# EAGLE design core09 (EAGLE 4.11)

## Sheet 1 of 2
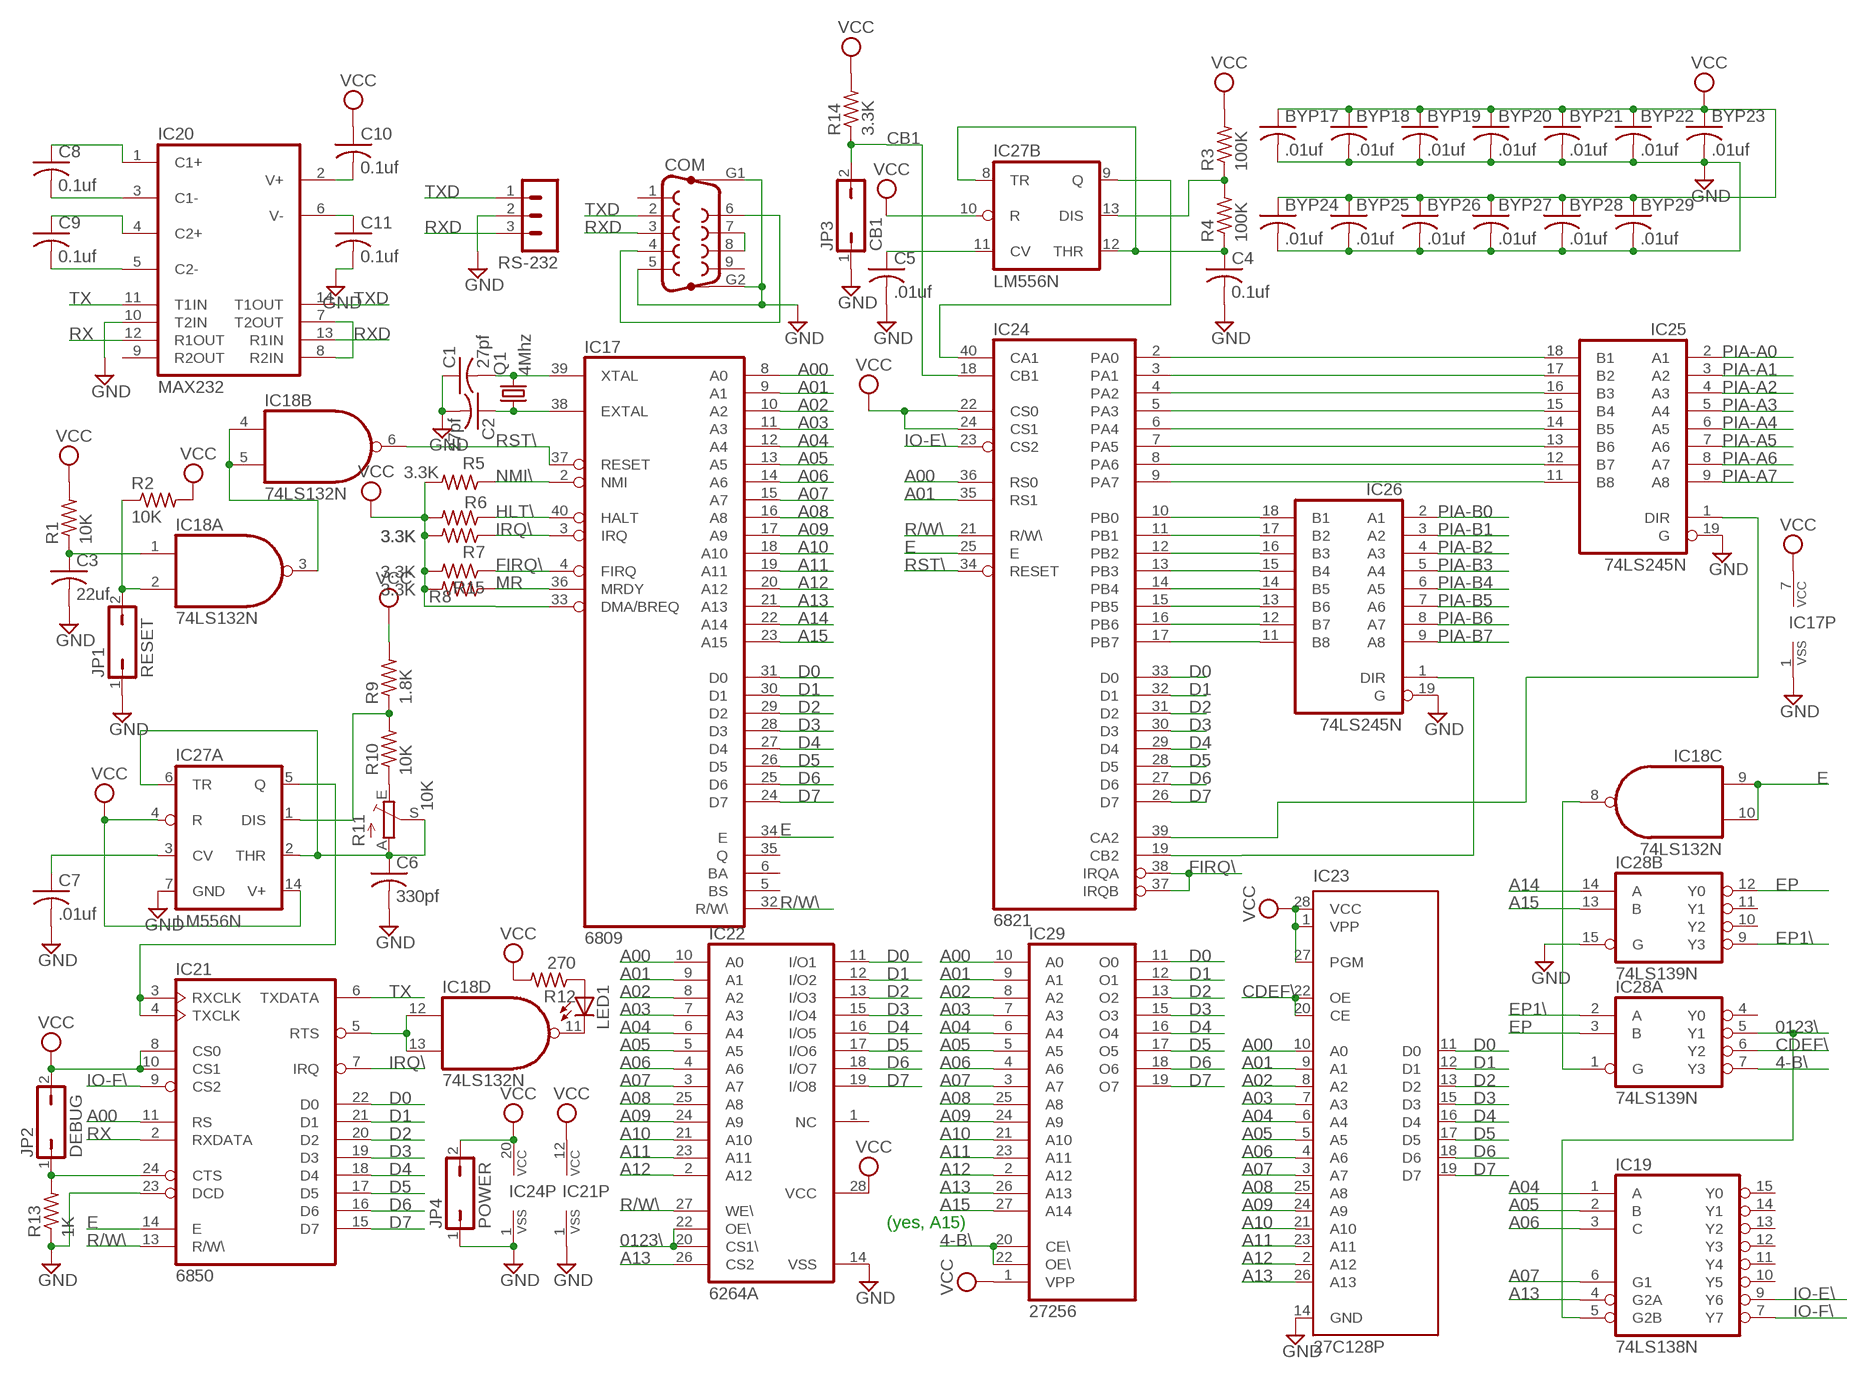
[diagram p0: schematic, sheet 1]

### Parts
BYP17  .01uf  C-US050-025X075  [C050-025X075]
BYP18  .01uf  C-US050-025X075  [C050-025X075]
BYP19  .01uf  C-US050-025X075  [C050-025X075]
BYP20  .01uf  C-US050-025X075  [C050-025X075]
BYP21  .01uf  C-US050-025X075  [C050-025X075]
BYP22  .01uf  C-US050-025X075  [C050-025X075]
BYP23  .01uf  C-US050-025X075  [C050-025X075]
BYP24  .01uf  C-US050-025X075  [C050-025X075]
BYP25  .01uf  C-US050-025X075  [C050-025X075]
BYP26  .01uf  C-US050-025X075  [C050-025X075]
BYP27  .01uf  C-US050-025X075  [C050-025X075]
BYP28  .01uf  C-US050-025X075  [C050-025X075]
BYP29  .01uf  C-US050-025X075  [C050-025X075]
C1  27pf  C-US050-025X075  [C050-025X075]
C2  27pf  C-US050-025X075  [C050-025X075]
C3  22uf  C-US102-043X133  [C102-043X133]
C4  0.1uf  C-US050-025X075  [C050-025X075]
C5  .01uf  C-US050-025X075  [C050-025X075]
C6  330pf  C-US050-025X075  [C050-025X075]
C7  .01uf  C-US050-025X075  [C050-025X075]
C8  0.1uf  C-US050-025X075  [C050-025X075]
C9  0.1uf  C-US050-025X075  [C050-025X075]
C10  0.1uf  C-US050-025X075  [C050-025X075]
C11  0.1uf  C-US050-025X075  [C050-025X075]
COM  F09HP  [F09HP]
IC17  6809  [DIL40]
IC18  74LS132N  74LS00N  [DIL14]
IC19  74LS138N  [DIL16]
IC20  MAX232  [DIL16]
IC21  6850  [DIL24]
IC22  6264A  [DIL28-6]
IC23  27C128P  [DIL28-6]
IC24  6821  [DIL40]
IC25  74LS245N  [DIL20]
IC26  74LS245N  [DIL20]
IC27  LM556N  [DIL14]
IC28  74LS139N  [DIL16]
IC29  27256  [DIL28]
JP1  RESET  JP1Q  [JP1]
JP2  DEBUG  JP1Q  [JP1]
JP3  CB1  JP1Q  [JP1]
JP4  POWER  JP1Q  [JP1]
LED1  LED3MM  [LED3MM]
Q1  4Mhz  CRYTALHC18U-V  [HC18U-V]
R1  10K  R-US_0207/7  [0207/7]
R2  10K  R-US_0207/7  [0207/7]
R3  100K  R-US_0207/7  [0207/7]
R4  100K  R-US_0207/7  [0207/7]
R5  3.3K  R-US_0207/7  [0207/7]
R6  3.3K  R-US_0207/7  [0207/7]
R7  3.3K  R-US_0207/7  [0207/7]
R8  3.3K  R-US_0207/7  [0207/7]
R9  1.8K  R-US_0207/7  [0207/7]
R10  10K  R-US_0207/7  [0207/7]
R11  10K  TRIM_EU-B90P  [SP19L]
R12  270  R-US_0207/7  [0207/7]
R13  1K  R-US_0207/7  [0207/7]
R14  3.3K  R-US_0207/7  [0207/7]
R15  3.3K  R-US_0207/7  [0207/7]
RS-232  MA03-1  [MA03-1]

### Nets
4-B\: IC28.7(A:Y3) IC29.20(CE\) IC29.22(OE\)
0123\: IC19.5(G2B) IC22.20(CS1\) IC22.22(OE\) IC28.5(A:Y1)
A00: IC17.8(A0) IC21.11(RS) IC22.10(A0) IC23.10(A0) IC24.36(RS0) IC29.10(A0)
A01: IC17.9(A1) IC22.9(A1) IC23.9(A1) IC24.35(RS1) IC29.9(A1)
A02: IC17.10(A2) IC22.8(A2) IC23.8(A2) IC29.8(A2)
A03: IC17.11(A3) IC22.7(A3) IC23.7(A3) IC29.7(A3)
A04: IC17.12(A4) IC19.1(A) IC22.6(A4) IC23.6(A4) IC29.6(A4)
A05: IC17.13(A5) IC19.2(B) IC22.5(A5) IC23.5(A5) IC29.5(A5)
A06: IC17.14(A6) IC19.3(C) IC22.4(A6) IC23.4(A6) IC29.4(A6)
A07: IC17.15(A7) IC19.6(G1) IC22.3(A7) IC23.3(A7) IC29.3(A7)
A08: IC17.16(A8) IC22.25(A8) IC23.25(A8) IC29.25(A8)
A09: IC17.17(A9) IC22.24(A9) IC23.24(A9) IC29.24(A9)
A10: IC17.18(A10) IC22.21(A10) IC23.21(A10) IC29.21(A10)
A11: IC17.19(A11) IC22.23(A11) IC23.23(A11) IC29.23(A11)
A12: IC17.20(A12) IC22.2(A12) IC23.2(A12) IC29.2(A12)
A13: IC17.21(A13) IC19.4(G2A) IC22.26(CS2) IC23.26(A13) IC29.26(A13)
A14: IC17.22(A14) IC28.14(B:A)
A15: IC17.23(A15) IC28.13(B:B) IC29.27(A14)
CB1: IC24.18(CB1) JP3.2 R14.1
CDEF\: IC23.20(CE) IC23.22(OE) IC28.6(A:Y2)
D0: IC17.31(D0) IC21.22(D0) IC22.11(I/O1) IC23.11(D0) IC24.33(D0) IC29.11(O0)
D1: IC17.30(D1) IC21.21(D1) IC22.12(I/O2) IC23.12(D1) IC24.32(D1) IC29.12(O1)
D2: IC17.29(D2) IC21.20(D2) IC22.13(I/O3) IC23.13(D2) IC24.31(D2) IC29.13(O2)
D3: IC17.28(D3) IC21.19(D3) IC22.15(I/O4) IC23.15(D3) IC24.30(D3) IC29.15(O3)
D4: IC17.27(D4) IC21.18(D4) IC22.16(I/O5) IC23.16(D4) IC24.29(D4) IC29.16(O4)
D5: IC17.26(D5) IC21.17(D5) IC22.17(I/O6) IC23.17(D5) IC24.28(D5) IC29.17(O5)
D6: IC17.25(D6) IC21.16(D6) IC22.18(I/O7) IC23.18(D6) IC24.27(D6) IC29.18(O6)
D7: IC17.24(D7) IC21.15(D7) IC22.19(I/O8) IC23.19(D7) IC24.26(D7) IC29.19(O7)
E: IC17.34(E) IC18.9(C:I0) IC18.10(C:I1) IC21.14(E) IC24.25(E)
EP: IC28.3(A:B) IC28.12(B:Y0)
EP1\: IC28.2(A:A) IC28.9(B:Y3)
FIRQ\ [Power]: IC17.4(FIRQ) IC24.37(IRQB) IC24.38(IRQA) R15.1
GND [Power]: BYP17.2 BYP18.2 BYP19.2 BYP20.2 BYP21.2 BYP22.2 BYP23.2 BYP24.2 BYP25.2 BYP26.2 BYP27.2 BYP28.2 BYP29.2 C1.1 C2.2 C3.2 C4.2 C5.2 C6.2 C7.2 C11.2 COM.5 COM.G1 COM.G2 IC17.1(VSS) IC20.10(T2IN) IC21.1(VSS) IC21.23(DCD) IC22.14(VSS) IC23.14(GND) IC24.1(VSS) IC25.19(G) IC26.19(G) IC27.7(A:GND) IC28.15(B:G) JP1.1 JP3.1 JP4.1 R13.1 RS-232.2 ; also sheet 2
HLT\: IC17.40(HALT) R5.1
IO-E\: IC19.9(Y6) IC24.23(CS2)
IO-F\: IC19.7(Y7) IC21.9(CS2)
IRQ\: IC17.3(IRQ) IC21.7(IRQ) R7.1
MR: IC17.36(MRDY) R8.1
N$1: COM.4 COM.6
N$3: C2.1 IC17.38(EXTAL) Q1.1
N$4: C1.2 IC17.39(XTAL) Q1.2
N$5: IC24.2(PA0) IC25.18(B1)
N$6: IC18.3(A:O) IC18.4(B:I0) IC18.5(B:I1)
N$21: C3.1 IC18.1(A:I0) R1.1
N$22: IC18.2(A:I1) JP1.2 R2.1
N$23: IC21.3(RXCLK) IC21.4(TXCLK) IC27.5(A:Q)
N$24: IC24.10(PB0) IC26.18(B1)
N$25: IC24.11(PB1) IC26.17(B2)
N$27: C6.1 IC27.2(A:THR) IC27.6(A:TR) R11.A R11.S
N$28: IC27.1(A:DIS) R9.1 R10.2
N$94: IC24.12(PB2) IC26.16(B3)
N$124: IC24.13(PB3) IC26.15(B4)
N$125: IC24.14(PB4) IC26.14(B5)
N$126: IC24.15(PB5) IC26.13(B6)
N$127: IC24.16(PB6) IC26.12(B7)
N$128: IC24.17(PB7) IC26.11(B8)
N$129: IC24.3(PA1) IC25.17(B2)
N$130: IC24.4(PA2) IC25.16(B3)
N$131: IC24.5(PA3) IC25.15(B4)
N$132: IC24.6(PA4) IC25.14(B5)
N$133: IC24.7(PA5) IC25.13(B6)
N$134: IC24.8(PA6) IC25.12(B7)
N$135: IC24.9(PA7) IC25.11(B8)
N$136: IC24.19(CB2) IC26.1(DIR)
N$137: IC24.39(CA2) IC25.1(DIR)
N$138: IC24.40(CA1) IC27.9(B:Q)
N$140: C4.1 IC27.8(B:TR) IC27.12(B:THR) R4.1
N$141: IC27.13(B:DIS) R3.1 R4.2
N$142: C5.1 IC27.11(B:CV)
N$143: R10.1 R11.E
N$145: COM.7 COM.8
N$147: IC18.12(D:I0) IC18.13(D:I1) IC21.5(RTS)
N$148: IC18.11(D:O) LED1.K(C)
N$149: LED1.A R12.1
N$150: IC21.24(CTS) JP2.1 R13.2
N$151: IC18.8(C:O) IC28.1(A:G)
N$153: IC20.7(T2OUT) IC20.8(R2IN)
N$154: C7.1 IC27.3(A:CV)
N$155: C9.2 IC20.5(C2-)
N$156: C9.1 IC20.4(C2+)
N$157: C8.2 IC20.3(C1-)
N$158: C8.1 IC20.1(C1+)
N$159: C11.1 IC20.6(V-)
N$160: C10.2 IC20.2(V+)
NMI\: IC17.2(NMI) R6.1
PIA-A0: IC25.2(A1) ; also sheet 2
PIA-A1: IC25.3(A2) ; also sheet 2
PIA-A2: IC25.4(A3) ; also sheet 2
PIA-A3: IC25.5(A4) ; also sheet 2
PIA-A4: IC25.6(A5) ; also sheet 2
PIA-A5: IC25.7(A6) ; also sheet 2
PIA-A6: IC25.8(A7) ; also sheet 2
PIA-A7: IC25.9(A8) ; also sheet 2
PIA-B0: IC26.2(A1) ; also sheet 2
PIA-B1: IC26.3(A2) ; also sheet 2
PIA-B2: IC26.4(A3) ; also sheet 2
PIA-B3: IC26.5(A4) ; also sheet 2
PIA-B4: IC26.6(A5) ; also sheet 2
PIA-B5: IC26.7(A6) ; also sheet 2
PIA-B6: IC26.8(A7) ; also sheet 2
PIA-B7: IC26.9(A8) ; also sheet 2
R/W\: IC17.32(R/W\) IC21.13(R/W\) IC22.27(WE\) IC24.21(R/W\)
RST\: IC17.37(RESET) IC18.6(B:O) IC24.34(RESET)
RX: IC20.12(R1OUT) IC21.2(RXDATA)
RXD: COM.3 IC20.13(R1IN) RS-232.3
TX: IC20.11(T1IN) IC21.6(TXDATA)
TXD: COM.2 IC20.14(T1OUT) RS-232.1
VCC [Power]: BYP17.1 BYP18.1 BYP19.1 BYP20.1 BYP21.1 BYP22.1 BYP23.1 BYP24.1 BYP25.1 BYP26.1 BYP27.1 BYP28.1 BYP29.1 C10.1 IC17.7(VCC) IC17.33(DMA/BREQ) IC21.8(CS0) IC21.10(CS1) IC21.12(VCC) IC22.28(VCC) IC23.1(VPP) IC23.27(PGM) IC23.28(VCC) IC24.20(VCC) IC24.22(CS0) IC24.24(CS1) IC27.4(A:R) IC27.10(B:R) IC27.14(A:V+) IC29.1(VPP) JP2.2 JP4.2 R1.2 R2.2 R3.2 R5.2 R6.2 R7.2 R8.2 R9.2 R12.2 R14.2 R15.2 ; also sheet 2
Unconnected: COM.1 COM.9 IC17.5(BS) IC17.6(BA) IC17.35(Q) IC19.10(Y5) IC19.11(Y4) IC19.12(Y3) IC19.13(Y2) IC19.14(Y1) IC19.15(Y0) IC20.9(R2OUT) IC22.1(NC) IC28.4(A:Y0) IC28.10(B:Y2) IC28.11(B:Y1)

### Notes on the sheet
- (yes, A15)

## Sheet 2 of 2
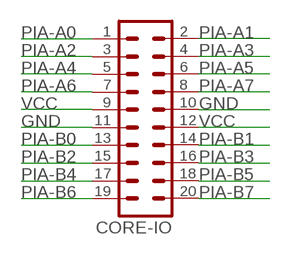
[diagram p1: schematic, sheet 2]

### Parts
CORE-IO  MA10-2  [MA10-2]

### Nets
GND [Power]: CORE-IO.10 CORE-IO.11 ; also sheet 1
PIA-A0: CORE-IO.1 ; also sheet 1
PIA-A1: CORE-IO.2 ; also sheet 1
PIA-A2: CORE-IO.3 ; also sheet 1
PIA-A3: CORE-IO.4 ; also sheet 1
PIA-A4: CORE-IO.5 ; also sheet 1
PIA-A5: CORE-IO.6 ; also sheet 1
PIA-A6: CORE-IO.7 ; also sheet 1
PIA-A7: CORE-IO.8 ; also sheet 1
PIA-B0: CORE-IO.13 ; also sheet 1
PIA-B1: CORE-IO.14 ; also sheet 1
PIA-B2: CORE-IO.15 ; also sheet 1
PIA-B3: CORE-IO.16 ; also sheet 1
PIA-B4: CORE-IO.17 ; also sheet 1
PIA-B5: CORE-IO.18 ; also sheet 1
PIA-B6: CORE-IO.19 ; also sheet 1
PIA-B7: CORE-IO.20 ; also sheet 1
VCC [Power]: CORE-IO.9 CORE-IO.12 ; also sheet 1

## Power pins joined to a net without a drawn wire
GND: IC18.7(P:GND) IC19.8(GND) IC20.15(GND) IC25.10(GND) IC26.10(GND) IC28.8(P:GND) IC29.14(GND)
VCC: IC18.14(P:VCC) IC19.16(VCC) IC20.16(VCC) IC25.20(VCC) IC26.20(VCC) IC28.16(P:VCC) IC29.28(VCC)

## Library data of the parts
BYP17-BYP29 C1-C11 = rcl:C-US: CAPACITOR, American symbol
COM = con-subd:F09HP: SUB-D
CORE-IO = con-lstb:MA10-2: PIN HEADER
IC17 = micro-motorola:6809: MICROCONTROLLER/MEMORY DEVICE
IC18 = 74xx-us:74*00: Quad 2-input NAND gate
IC19 = 74xx-us:74*138: 3-line to 8-line DECODER/DEMULTIPLEXER
IC20 = maxim:MAX232: RS232 TRANSEIVER
IC21 = micro-motorola:6850: MICROCONTROLLER/MEMORY DEVICE
IC22 = memory-hitachi:6264A: MEMORY
IC23 = microchip:27*128: CMOS EPROM 128 K (16 K x 8)
IC24 = micro-motorola:6821: MICROCONTROLLER/MEMORY DEVICE
IC25 IC26 = 74xx-us:74*245: Octal BUS TRANSCEIVER, 3-state
IC27 = linear:*556: Dual TIMER
IC28 = 74xx-us:74*139: Dual 2-line to 4-line DECODER/DEMULTIPLEXER
IC29 = memory:27256: MEMORY
JP1-JP4 = jumper:JP1Q: JUMPER
LED1 = led:LED: LED
Q1 = crystal:CRYTAL: CRYSTAL
R1-R10 R12-R15 = rcl:R-US_: RESISTOR, American symbol
R11 = pot:TRIM_EU-: POTENTIOMETER
RS-232 = con-lstb:MA03-1: PIN HEADER

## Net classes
1 Power: width 0.508 mm, drill 0.254 mm, clearance 0.254 mm

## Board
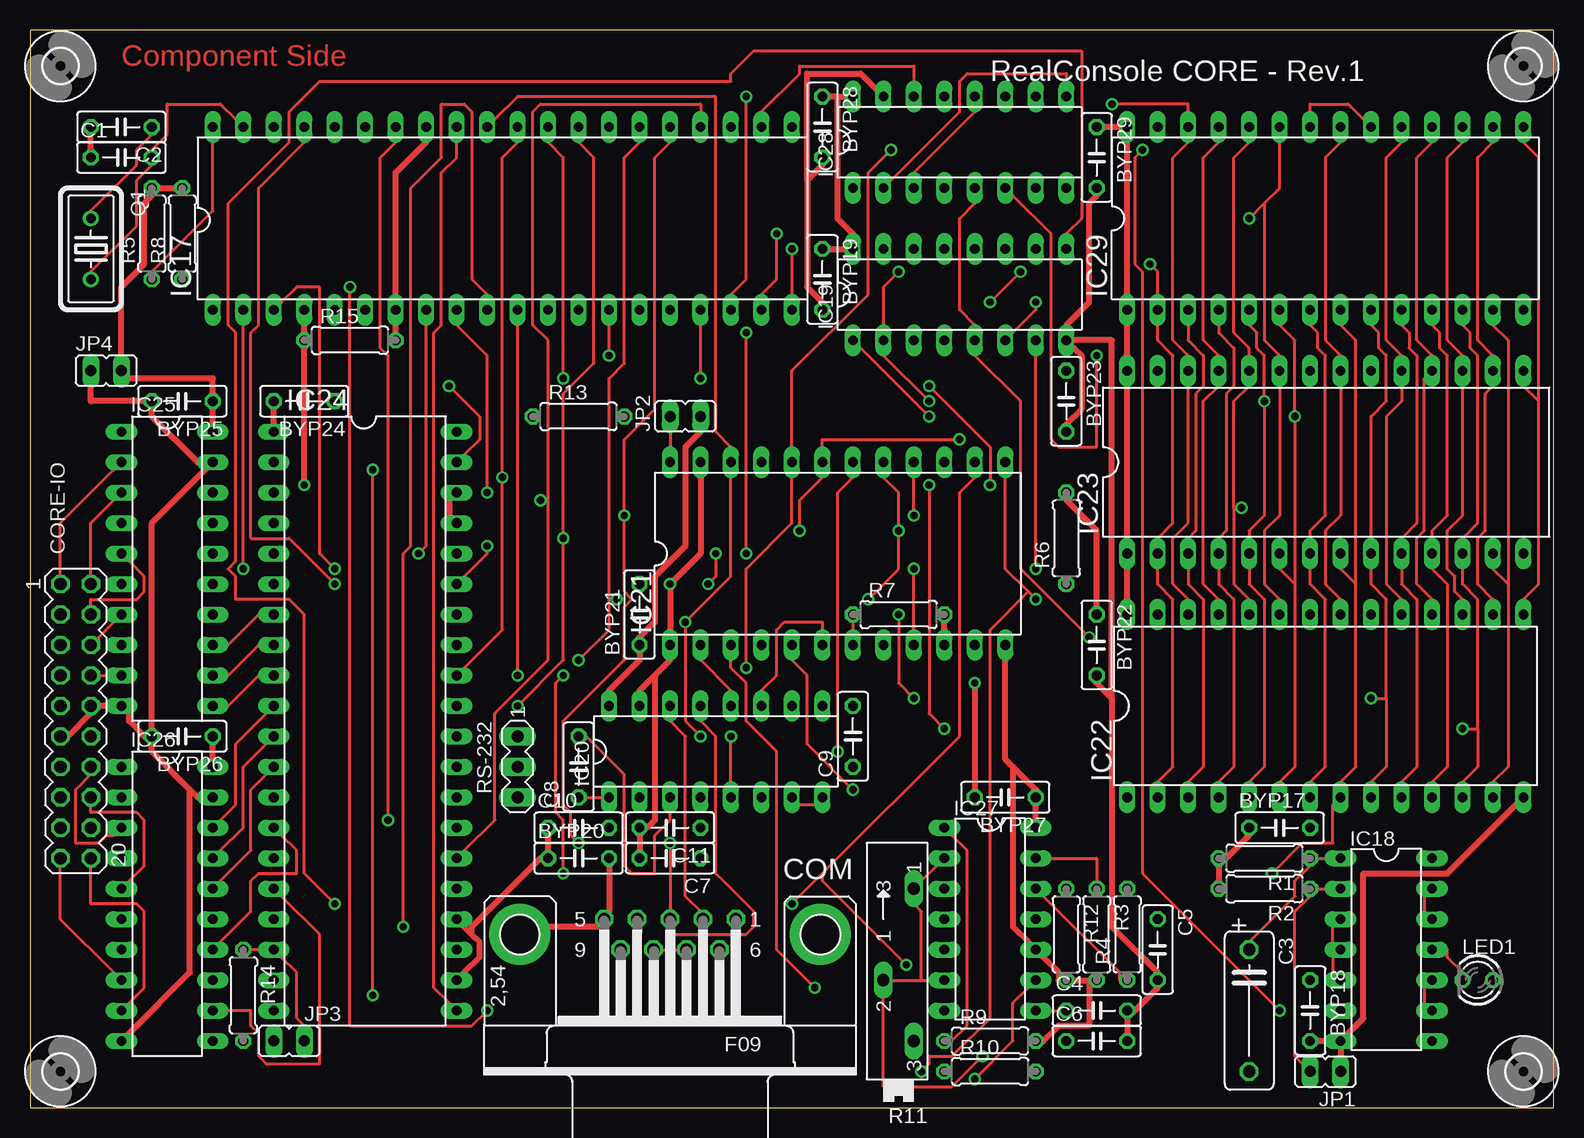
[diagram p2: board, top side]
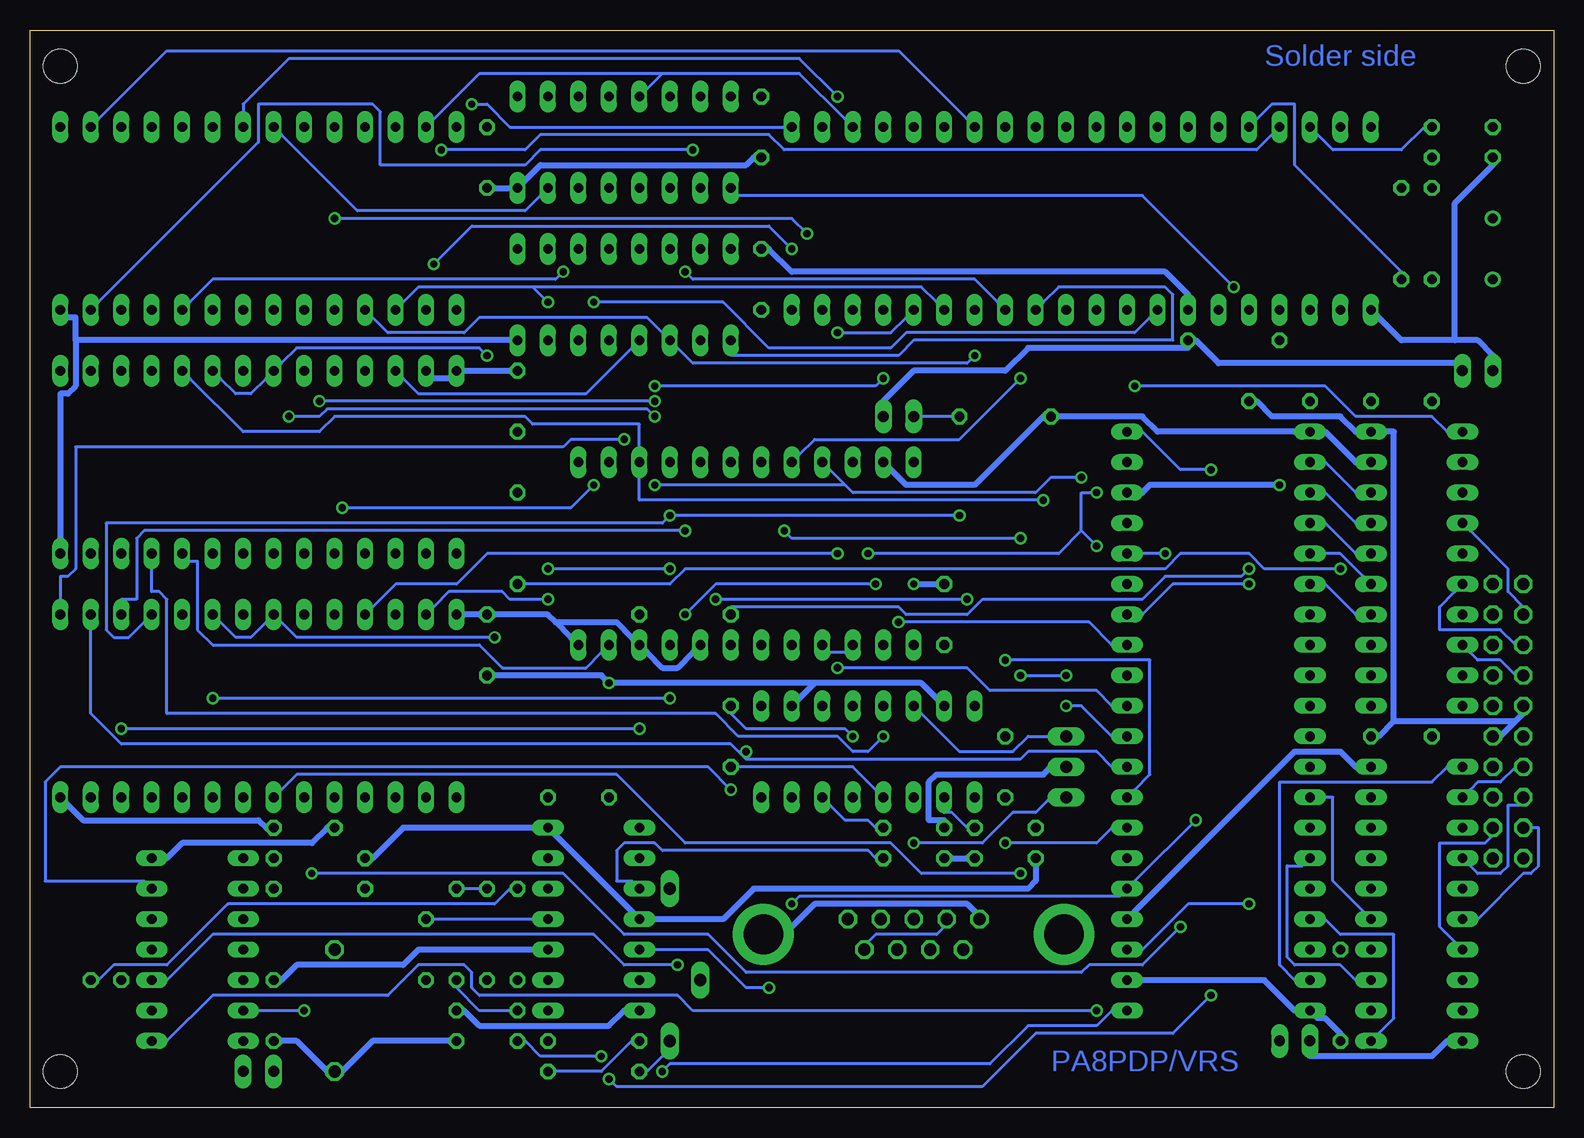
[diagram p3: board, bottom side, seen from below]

Size 126.98 x 89.84 mm. Coordinates in mm from the lower left corner, seen from the top.
Outline: 0,0 126.98,0 126.98,89.84 0,89.84 0,0
Copper layers (1*16): Top 0.035mm / dielectric 1.5mm / Bottom 0.035mm
Design rules "olimex10mil": minimum track width 10mil, minimum drill 24mil, track to track 10mil, track to pad 10mil, pad to pad 10mil, via to via 10mil, smd to smd 10mil, copper to edge 40mil, drill to drill 10mil, minimum pad ring 10mil, minimum via ring 8mil, stop-mask expansion 0mil, vias tented up to drill 0mil, thermal gap 10mil

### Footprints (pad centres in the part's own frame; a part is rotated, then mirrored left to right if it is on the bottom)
C050-025X075 = drill 0.813 octagon: 1 -2.54,0; 2 2.54,0
C102-043X133 = drill 1.016 octagon: 1 -5.08,0; 2 5.08,0
F09HP = drill 1.016 octagon: 1 -5.486,-1.27; 2 -2.743,-1.27; 3 0,-1.27; 4 2.743,-1.27; 5 5.486,-1.27; 6 -4.115,1.27; 7 -1.372,1.27; 8 1.372,1.27; 9 4.115,1.27 | drill 3.302 pad 5.08 round: G1 -12.522,0; G2 12.522,0
MA10-2 = drill 1.016 octagon: 1 -11.43,-1.27; 2 -11.43,1.27; 3 -8.89,-1.27; 4 -8.89,1.27; 5 -6.35,-1.27; 6 -6.35,1.27; 7 -3.81,-1.27; 8 -3.81,1.27; 9 -1.27,-1.27; 10 -1.27,1.27; 11 1.27,-1.27; 12 1.27,1.27; 13 3.81,-1.27; 14 3.81,1.27; 15 6.35,-1.27; 16 6.35,1.27; 17 8.89,-1.27; 18 8.89,1.27; 19 11.43,-1.27; 20 11.43,1.27
DIL40 = drill 0.813 long: 1 -24.13,-7.62; 2 -21.59,-7.62; 3 -19.05,-7.62; 4 -16.51,-7.62; 5 -13.97,-7.62; 6 -11.43,-7.62; 7 -8.89,-7.62; 8 -6.35,-7.62; 9 -3.81,-7.62; 10 -1.27,-7.62; 11 1.27,-7.62; 12 3.81,-7.62; 13 6.35,-7.62; 14 8.89,-7.62; 15 11.43,-7.62; 16 13.97,-7.62; 17 16.51,-7.62; 18 19.05,-7.62; 19 21.59,-7.62; 20 24.13,-7.62; 21 24.13,7.62; 22 21.59,7.62; 23 19.05,7.62; 24 16.51,7.62; 25 13.97,7.62; 26 11.43,7.62; 27 8.89,7.62; 28 6.35,7.62; 29 3.81,7.62; 30 1.27,7.62; 31 -1.27,7.62; 32 -3.81,7.62; 33 -6.35,7.62; 34 -8.89,7.62; 35 -11.43,7.62; 36 -13.97,7.62; 37 -16.51,7.62; 38 -19.05,7.62; 39 -21.59,7.62; 40 -24.13,7.62
DIL14 = drill 0.813 long: 1 -7.62,-3.81; 2 -5.08,-3.81; 3 -2.54,-3.81; 4 0,-3.81; 5 2.54,-3.81; 6 5.08,-3.81; 7 7.62,-3.81; 8 7.62,3.81; 9 5.08,3.81; 10 2.54,3.81; 11 0,3.81; 12 -2.54,3.81; 13 -5.08,3.81; 14 -7.62,3.81
DIL16 = drill 0.813 long: 1 -8.89,-3.81; 2 -6.35,-3.81; 3 -3.81,-3.81; 4 -1.27,-3.81; 5 1.27,-3.81; 6 3.81,-3.81; 7 6.35,-3.81; 8 8.89,-3.81; 9 8.89,3.81; 10 6.35,3.81; 11 3.81,3.81; 12 1.27,3.81; 13 -1.27,3.81; 14 -3.81,3.81; 15 -6.35,3.81; 16 -8.89,3.81
DIL24 = drill 0.813 long: 1 -13.97,-7.62; 2 -11.43,-7.62; 3 -8.89,-7.62; 4 -6.35,-7.62; 5 -3.81,-7.62; 6 -1.27,-7.62; 7 1.27,-7.62; 8 3.81,-7.62; 9 6.35,-7.62; 10 8.89,-7.62; 11 11.43,-7.62; 12 13.97,-7.62; 13 13.97,7.62; 14 11.43,7.62; 15 8.89,7.62; 16 6.35,7.62; 17 3.81,7.62; 18 1.27,7.62; 19 -1.27,7.62; 20 -3.81,7.62; 21 -6.35,7.62; 22 -8.89,7.62; 23 -11.43,7.62; 24 -13.97,7.62
DIL28-6 = drill 0.813 long: 1 -16.51,-7.62; 2 -13.97,-7.62; 3 -11.43,-7.62; 4 -8.89,-7.62; 5 -6.35,-7.62; 6 -3.81,-7.62; 7 -1.27,-7.62; 8 1.27,-7.62; 9 3.81,-7.62; 10 6.35,-7.62; 11 8.89,-7.62; 12 11.43,-7.62; 13 13.97,-7.62; 14 16.51,-7.62; 15 16.51,7.62; 16 13.97,7.62; 17 11.43,7.62; 18 8.89,7.62; 19 6.35,7.62; 20 3.81,7.62; 21 1.27,7.62; 22 -1.27,7.62; 23 -3.81,7.62; 24 -6.35,7.62; 25 -8.89,7.62; 26 -11.43,7.62; 27 -13.97,7.62; 28 -16.51,7.62
DIL20 = drill 0.813 long: 1 -11.43,-3.81; 2 -8.89,-3.81; 3 -6.35,-3.81; 4 -3.81,-3.81; 5 -1.27,-3.81; 6 1.27,-3.81; 7 3.81,-3.81; 8 6.35,-3.81; 9 8.89,-3.81; 10 11.43,-3.81; 11 11.43,3.81; 12 8.89,3.81; 13 6.35,3.81; 14 3.81,3.81; 15 1.27,3.81; 16 -1.27,3.81; 17 -3.81,3.81; 18 -6.35,3.81; 19 -8.89,3.81; 20 -11.43,3.81
DIL28 = drill 0.813 long: 1 -16.51,-7.62; 2 -13.97,-7.62; 3 -11.43,-7.62; 4 -8.89,-7.62; 5 -6.35,-7.62; 6 -3.81,-7.62; 7 -1.27,-7.62; 8 1.27,-7.62; 9 3.81,-7.62; 10 6.35,-7.62; 11 8.89,-7.62; 12 11.43,-7.62; 13 13.97,-7.62; 14 16.51,-7.62; 15 16.51,7.62; 16 13.97,7.62; 17 11.43,7.62; 18 8.89,7.62; 19 6.35,7.62; 20 3.81,7.62; 21 1.27,7.62; 22 -1.27,7.62; 23 -3.81,7.62; 24 -6.35,7.62; 25 -8.89,7.62; 26 -11.43,7.62; 27 -13.97,7.62; 28 -16.51,7.62
JP1 = drill 0.914 long: 1 0,-1.27; 2 0,1.27
LED3MM = drill 0.813 octagon: A -1.27,0; K 1.27,0
HC18U-V = drill 0.813 round: 1 -2.54,0; 2 2.54,0
0207/7 = drill 0.813 octagon: 1 -3.81,0; 2 3.81,0
SP19L = drill 1.016 long: A 5.715,-1.27; E -6.985,-1.27; S -1.905,1.27
MA03-1 = drill 1.016 long: 1 -2.54,0; 2 0,0; 3 2.54,0
2,8 = hole 2.8: 0,0

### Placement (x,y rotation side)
BYP17  104.14,23.33 0 top
BYP18  106.68,8.09 270 top
BYP19  66.04,69.05 270 top
BYP20  45.71,20.79 0 top
BYP21  50.79,41.11 90 top
BYP22  88.9,38.57 270 top
BYP23  86.36,58.89 270 top
BYP24  22.86,58.89 180 top
BYP25  12.69,58.89 180 top
BYP26  12.69,30.95 180 top
BYP27  81.28,25.87 180 top
BYP28  66.04,81.75 270 top
BYP29  88.9,79.21 270 top
C1  7.62,79.21 0 top
C2  7.62,81.75 180 top
C3  101.59,8.09 270 top
C4  88.9,8.09 0 top
C5  93.98,13.17 270 top
C6  88.9,5.55 0 top
C7  53.34,20.79 180 top
C8  45.71,28.41 90 top
C9  68.58,30.95 90 top
C10  45.71,23.33 0 top
C11  53.34,23.33 180 top
COM  53.34,14.44 180 top
CORE-IO  3.81,32.22 270 top
IC17  39.36,74.13 0 top
IC18  113.03,13.17 270 top
IC19  77.47,67.78 0 top
IC20  57.14,29.68 0 top
IC21  67.31,46.19 0 top
IC22  107.95,33.49 0 top
IC23  107.95,53.81 0 top
IC24  27.94,32.22 270 top
IC25  11.42,44.92 270 top
IC26  11.42,16.98 270 top
IC27  80.01,15.71 270 top
IC28  77.47,80.48 0 top
IC29  107.95,74.13 0 top
JP1  107.95,3.01 90 top
JP2  54.6,57.62 270 top
JP3  21.59,5.55 270 top
JP4  6.34,61.43 270 top
LED1  120.65,10.63 180 top
Q1  5.08,71.59 270 top
R1  102.87,20.79 180 top
R2  102.87,18.25 180 top
R3  88.9,14.44 270 top
R4  91.44,14.44 90 top
R5  10.15,72.86 90 top
R6  86.36,47.46 90 top
R7  72.39,41.11 0 top
R8  12.69,72.86 90 top
R9  80.01,5.55 0 top
R10  80.01,3.01 0 top
R11  72.39,12.54 90 top
R12  86.36,14.44 270 top
R13  45.71,57.62 0 top
R14  17.78,9.36 270 top
R15  26.67,63.97 0 top
RS-232  40.63,28.41 270 top
U$3  [2,8]  2.54,86.83 0 top
U$4  [2,8]  2.54,3.01 0 top
U$5  [2,8]  124.45,86.83 0 top
U$6  [2,8]  124.45,3.01 0 top

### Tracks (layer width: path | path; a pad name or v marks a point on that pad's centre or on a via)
4-B\
  Top 0.254: IC29.20 111.12,82.39 109.85,83.66 106.68,83.66 106.68,83.02 IC29.22
  Bottom 0.254: IC28.7 84.45,76.03 85.72,74.77 99.69,74.77 106.04,81.11 IC29.22
0123\  (via drill 0.61)
  Top 0.254: IC28.5 78.73,75.4 77.47,74.13 77.47,66.51 78.73,65.24 IC19.5 78.73,62.7 82.55,58.89 82.55,44.92 v88.26,39.2
  Bottom 0.254: IC22.20 111.12,40.48 109.85,39.2 108.58,39.2 107.31,40.48 IC22.22 106.04,40.48 104.77,39.2 v88.26,39.2
A00  (via drill 0.61)
  Top 0.254: v32.38,46.19 33.02,46.82 33.02,65.24 IC17.8 | IC22.10 114.3,27.14 115.56,28.41 115.56,42.38 114.3,43.65 114.3,44.92 IC23.10 114.3,47.46 115.56,48.73 115.56,62.7 114.93,63.34 114.93,64.61 114.3,65.24 IC29.10 | v80.01,67.14 v82.55,69.69
  Bottom 0.254: v32.38,46.19 34.28,46.19 IC24.36 | IC21.11 79.37,37.94 80.64,36.66 87.62,36.66 89.53,38.57 111.76,38.57 113.03,39.84 113.03,45.55 113.66,45.55 IC23.10 | v80.01,67.14 69.21,67.14 65.4,63.34 55.24,63.34 53.97,64.61 34.92,64.61 33.65,65.88 IC17.8 | v82.55,69.69 83.18,69.05 111.76,69.05 113.66,67.14 IC29.10
A01  (via drill 0.61)
  Top 0.254: v38.09,46.82 38.09,46.19 36.19,44.28 IC24.35 | v38.09,51.27 38.09,62.7 35.55,65.24 IC17.9 | IC29.9 111.76,65.24 112.39,64.61 112.39,63.34 113.03,62.7 113.03,58.89 111.76,57.62 111.76,47.46 IC23.9 111.76,44.92 111.76,43.65 113.03,42.38 113.03,34.12 | 113.03,34.12 113.03,28.41 111.76,27.14 IC22.9 | v111.76,34.12 113.03,34.12 | v73.66,34.12 72.39,35.39 v72.39,41.11 | v56.51,43.65 57.14,44.28 v57.14,46.19
  Bottom 0.254: v38.09,46.82 39.36,48.09 | 39.36,48.09 39.36,51.27 v38.09,51.27 | v73.66,34.12 v111.76,34.12 | v72.39,41.11 69.84,43.65 v56.51,43.65 | v57.14,46.19 41.27,46.19 39.36,48.09
A02  (via drill 0.61)
  Top 0.254: 110.48,43.65 110.48,28.41 109.22,27.14 IC22.8 108.58,25.23 108.58,22.06 106.04,22.06 v103.5,19.52 | 110.48,43.65 109.22,44.92 IC23.8 | v31.11,15.08 31.11,46.19 31.75,46.82 31.75,76.67 34.28,79.21 34.28,83.66 36.19,83.66 36.82,83.02 36.82,69.05 38.09,67.78 IC17.10 | 110.48,43.65 110.48,63.97 109.22,65.24 IC29.8
  Bottom 0.254: v31.11,15.08 34.28,11.9 38.73,11.9 39.36,11.27 67.31,11.27 70.48,14.44 77.47,14.44 82.55,19.52 v103.5,19.52
A03  (via drill 0.61)
  Top 0.254: IC22.7 106.68,27.14 107.95,28.41 107.95,42.38 106.68,43.65 106.68,44.92 IC23.7 106.68,47.46 106.68,48.09 107.95,49.37 107.95,62.7 107.31,63.34 107.31,64.61 106.68,65.24 IC29.7 | v40.63,36.03 40.63,65.24 IC17.11 | v44.45,36.03 43.81,35.39 43.81,24.6 44.45,23.96 v44.45,19.52
  Bottom 0.254: v44.45,36.03 v40.63,36.03 | v44.45,19.52 52.7,19.52 55.24,22.06 72.39,22.06 78.1,27.77 104.77,27.77 106.04,26.5 IC22.7
A04  (via drill 0.61)
  Top 0.254: 105.41,43.65 105.41,28.41 104.14,27.14 IC22.6 | 105.41,43.65 104.14,44.92 IC23.6 | 105.41,43.65 v105.41,57.62 105.41,63.97 104.14,65.24 IC29.6 | v74.93,57.62 69.21,63.34 IC19.1
  Bottom 0.254: IC17.12 42.54,67.14 41.27,68.41 32.38,68.41 31.75,67.78 31.75,63.97 53.34,63.97 54.6,62.7 68.58,62.7 IC19.1 | v74.93,57.62 75.56,58.25 102.23,58.25 102.87,57.62 v105.41,57.62
A05  (via drill 0.61)
  Top 0.254: v72.39,69.69 71.12,68.41 71.12,65.24 IC19.2 71.12,62.7 v74.93,58.89 | IC22.5 101.59,27.14 102.87,28.41 102.87,42.38 101.59,43.65 101.59,44.92 IC23.5 101.59,47.46 101.59,48.09 102.87,49.37 v102.87,58.89 102.87,62.7 102.23,63.34 102.23,64.61 101.59,65.24 IC29.5
  Bottom 0.254: v72.39,69.69 71.75,69.05 48.25,69.05 46.35,67.14 IC17.13 | v74.93,58.89 v102.87,58.89
A06  (via drill 0.61)
  Top 0.254: IC22.4 99.06,27.14 100.33,28.41 100.33,42.38 99.06,43.65 99.06,44.92 IC23.4 99.06,47.46 99.69,48.09 99.69,59.52 100.33,60.16 100.33,63.34 99.06,64.61 99.06,65.24 IC29.4 | v48.25,62.7 48.25,65.24 IC17.14
  Bottom 0.254: IC29.4 98.42,65.88 97.15,64.61 90.8,64.61 89.53,65.88 75.56,65.88 74.29,64.61 IC19.3 73.02,63.34 71.75,62.06 48.89,62.06 v48.25,62.7
A07  (via drill 0.61)
  Top 0.254: IC22.3 96.52,27.14 97.79,28.41 97.79,42.38 96.52,43.65 96.52,44.92 IC23.3 96.52,47.46 97.15,48.09 97.15,59.52 97.79,60.16 97.79,62.7 96.52,63.97 96.52,65.24 IC29.3 | v83.81,67.14 83.81,66.51 81.91,64.61 IC19.6
  Bottom 0.254: 85.09,68.41 v83.81,67.14 | 85.09,68.41 94.61,68.41 95.88,67.14 IC29.3 | 85.09,68.41 52.7,68.41 51.43,67.14 IC17.15
A08  (via drill 0.61)
  Top 0.254: IC22.25 99.06,42.38 97.79,43.65 97.79,58.89 99.06,60.16 IC23.25 99.06,62.7 97.79,63.97 97.79,79.21 99.06,80.48 IC29.25 | v59.68,46.19 v59.68,64.61
  Bottom 0.254: v59.68,64.61 55.24,64.61 53.97,65.88 IC17.16 | v59.68,46.19 88.9,46.19 91.44,43.65 96.52,43.65 98.42,41.74 IC22.25
A09  (via drill 0.61)
  Top 0.254: 100.33,50 100.33,58.89 101.59,60.16 IC23.24 101.59,62.7 101.59,63.34 100.33,64.61 100.33,79.21 101.59,80.48 IC29.24 | 100.33,50 100.33,43.65 101.59,42.38 IC22.24 | v55.88,60.8 55.88,65.24 IC17.17 | v74.93,60.16 80.01,55.08 v80.01,51.91 | v100.96,50 100.33,50
  Bottom 0.254: v55.88,60.8 56.51,60.16 v74.93,60.16 | v80.01,51.91 81.91,50 v100.96,50
A10  (via drill 0.61)
  Top 0.254: IC22.21 109.22,42.38 107.95,43.65 107.95,48.09 109.22,49.37 109.22,60.16 IC23.21 109.22,62.7 107.95,63.97 107.95,79.21 109.22,80.48 IC29.21 | v59.68,84.29 59.68,69.05 58.41,67.78 IC17.18
  Bottom 0.254: v59.68,84.29 62.86,87.47 105.41,87.47 109.22,83.66 109.22,83.02 IC29.21
A11  (via drill 0.61)
  Top 0.254: IC22.23 104.14,42.38 102.87,43.65 102.87,48.09 104.14,49.37 104.14,60.16 IC23.23 104.14,62.7 102.87,63.97 102.87,75.4 | v62.22,72.86 62.22,69.05 60.95,67.78 IC17.19 | 102.87,75.4 104.14,76.67 104.14,80.48 IC29.23 | v101.59,74.13 102.87,75.4
  Bottom 0.254: v62.22,72.86 63.49,74.13 v101.59,74.13
A12  (via drill 0.61)
  Top 0.254: IC22.2 93.98,27.14 95.25,28.41 95.25,42.38 93.98,43.65 93.98,44.92 IC23.2 93.98,47.46 95.25,48.73 95.25,62.7 93.98,63.97 93.98,65.24 IC29.2 93.98,67.78 93.98,69.69 v93.34,70.32 | v63.49,71.59 63.49,67.78 IC17.20
  Bottom 0.254: v63.49,71.59 65.4,73.5 90.17,73.5 v93.34,70.32
A13  (via drill 0.61)
  Top 0.254: v90.17,83.66 96.52,83.66 96.52,83.02 IC29.26 96.52,80.48 95.25,79.21 95.25,63.97 96.52,62.7 IC23.26 96.52,60.16 96.52,48.73 95.25,47.46 95.25,43.65 96.52,42.38 IC22.26
  Bottom 0.254: v90.17,83.66 88.9,83.66 86.99,81.75 64.13,81.75 IC17.21 | IC19.4 76.83,63.34 80.64,59.52 94.61,59.52 95.88,60.8 IC23.26
A14
  Top 0.254: IC17.22 60.95,83.02 64.13,86.19 64.13,86.83 73.66,86.83 73.66,85.56 IC28.14
A15
  Bottom 0.254: 74.29,86.19 62.86,86.19 59.05,82.39 IC17.23 | 74.29,86.19 75.56,84.92 IC28.13 | 74.29,86.19 89.53,86.19 93.34,82.39 IC29.27
CB1
  Top 0.254: R14.1 18.41,13.17 19.05,13.17 IC24.18 20.95,12.54 22.22,11.27 22.22,7.46 22.86,6.82 JP3.2
CDEF\  (via drill 0.61)
  Top 0.254: v88.9,62.7 88.9,55.08 85.72,55.08 85.09,55.71 85.09,72.86 81.91,76.03 IC28.6
  Bottom 0.254: IC23.20 111.12,60.8 109.85,59.52 108.58,59.52 107.31,60.8 IC23.22 106.04,62.06 104.77,63.34 89.53,63.34 v88.9,62.7
D0  (via drill 0.61)
  Top 0.254: IC22.11 116.84,27.14 118.11,28.41 118.11,43.65 116.84,44.92 IC23.11 116.84,47.46 116.84,48.09 118.11,49.37 118.11,62.7 117.47,63.34 117.47,64.61 116.84,65.24 IC29.11 | IC17.31 38.73,82.39 40.63,84.29 57.14,84.29 57.14,56.35 58.41,55.08 IC21.22 58.41,52.54 58.41,44.28 v54.6,40.48 54.6,32.22 v55.88,30.95
  Bottom 0.254: v54.6,40.48 38.73,40.48 36.82,38.57 IC24.33 | v55.88,30.95 57.14,29.68 58.41,29.68 59.68,30.95 67.94,30.95 69.84,32.85 115.56,32.85 115.56,42.38 116.2,43.02 116.84,43.02 116.84,44.92 IC23.11
D1  (via drill 0.61)
  Top 0.254: 120.65,31.58 120.65,42.38 119.38,43.65 119.38,44.92 IC23.12 119.38,47.46 120.65,48.73 120.65,62.7 120.01,63.34 120.01,64.61 119.38,65.24 IC29.12 | 120.65,31.58 120.65,28.41 119.38,27.14 IC22.12 | IC24.32 36.19,36.66 39.36,39.84 v39.36,52.54 39.36,79.21 40.63,80.48 IC17.30 | v119.38,31.58 120.65,31.58 | v76.2,31.58 74.93,32.85 v74.93,51.91
  Bottom 0.254: 59.05,51.91 58.41,51.27 43.17,51.27 41.9,52.54 v39.36,52.54 | 59.05,51.91 60.32,53.17 IC21.21 | v76.2,31.58 v119.38,31.58 | 59.05,51.91 v74.93,51.91
D2  (via drill 0.61)
  Top 0.254: 123.19,43.65 123.19,28.41 121.92,27.14 IC22.13 | 123.19,43.65 121.92,44.92 IC23.13 | 123.19,43.65 123.19,63.97 121.92,65.24 IC29.13 | v59.68,36.66 59.68,44.92 63.49,48.73 63.49,52.54 IC21.20 63.49,55.08 63.49,61.43 69.84,67.78 69.84,77.94 v71.75,79.84 | v44.45,60.8 44.45,79.21 43.17,80.48 IC17.29
  Bottom 0.254: v59.68,36.66 48.89,36.66 46.98,34.76 38.09,34.76 36.82,33.49 IC24.31 | v44.45,60.8 49.52,55.71 61.59,55.71 62.86,54.45 IC21.20 | v71.75,79.84 84.45,79.84 85.72,78.58 97.79,78.58 97.79,83.02 98.42,83.66 107.95,83.66 107.95,80.48 121.28,67.14 IC29.13
D3  (via drill 0.61)
  Top 0.254: 125.73,58.89 125.73,43.65 124.45,42.38 IC22.15 | 125.73,58.89 124.45,60.16 IC23.15 | 125.73,58.89 125.73,79.21 124.45,80.48 IC29.15 | v40.63,33.49 44.45,37.3 v44.45,47.46 44.45,59.52 46.98,62.06 46.98,79.21 45.71,80.48 IC17.28 | v64.13,48.09 64.13,50.63 66.04,52.54 IC21.19 66.04,55.08 66.04,55.71 v77.47,55.71
  Bottom 0.254: v40.63,33.49 39.36,33.49 36.82,30.95 IC24.30 | v64.13,48.09 63.49,47.46 v44.45,47.46 | v77.47,55.71 81.91,55.71 82.55,55.08 123.19,55.08 123.19,44.92 123.82,44.28 124.45,44.28 124.45,42.38 IC22.15
D4  (via drill 0.61)
  Top 0.254: IC29.16 121.92,80.48 120.65,79.21 120.65,63.97 121.92,62.7 IC23.16 121.92,60.16 121.28,59.52 121.28,48.09 120.65,47.46 120.65,43.65 121.92,42.38 IC22.16 | v67.31,29.68 67.31,51.27 68.58,52.54 IC21.18
  Bottom 0.254: IC17.27 48.89,82.39 54.6,88.1 115.56,88.1 121.28,82.39 IC29.16 | 67.94,29.68 68.58,30.31 119.38,30.31 121.92,32.85 121.92,39.84 IC22.16 | 67.94,29.68 67.31,29.04 44.45,29.04 43.81,29.68 38.09,29.68 36.82,28.41 IC24.29 | 67.94,29.68 v67.31,29.68
D5  (via drill 0.61)
  Top 0.254: v45.71,37.3 48.25,39.84 48.25,42.38 | 48.25,42.38 48.25,60.8 49.52,62.06 49.52,79.21 50.79,80.48 IC17.26 | IC22.17 119.38,42.38 118.74,43.02 118.74,44.28 118.11,44.92 118.11,48.09 119.38,49.37 119.38,60.16 IC23.17 119.38,62.7 118.11,63.97 118.11,79.21 119.38,80.48 IC29.17 | IC21.17 71.12,52.54 72.39,51.27 v72.39,48.09 72.39,44.92 v69.84,42.38 | 48.25,42.38 v48.89,42.38
  Bottom 0.254: v45.71,37.3 33.65,37.3 33.65,27.77 34.92,26.5 IC24.28 | v72.39,48.09 117.47,48.09 118.11,47.46 118.11,42.38 119.38,42.38 IC22.17 | v48.89,42.38 v69.84,42.38
D6  (via drill 0.61)
  Top 0.254: IC22.18 116.84,42.38 115.56,43.65 115.56,47.46 116.2,48.09 116.2,60.8 IC23.18 116.84,62.7 115.56,63.97 115.56,79.21 116.84,80.48 IC29.18 | v45.71,22.06 45.08,22.7 45.08,24.6 44.45,25.23 44.45,32.22 49.52,37.3 49.52,41.74 50.16,42.38 49.52,43.02 v49.52,49.37 49.52,55.71 52.06,58.25 52.06,79.21 53.34,80.48 IC17.25 | v73.66,49.37 73.66,52.54 IC21.16
  Bottom 0.254: v45.71,22.06 38.09,22.06 36.82,23.33 IC24.27 | v49.52,49.37 v73.66,49.37 74.29,48.73 120.65,48.73 120.65,39.84 120.01,39.2 118.74,39.2 117.47,40.48 IC22.18
D7  (via drill 0.61)
  Top 0.254: IC22.19 114.3,42.38 113.03,43.65 113.03,57.62 114.3,58.89 114.3,60.16 IC23.19 114.3,62.7 113.03,63.97 113.03,79.21 114.3,80.48 IC29.19 | 43.17,50.63 43.17,63.97 41.9,65.24 41.9,83.02 42.54,83.66 55.88,83.66 55.88,83.02 IC17.24 | 43.17,50.63 43.17,37.3 38.73,32.85 38.73,23.96 36.19,21.42 IC24.26 | 43.17,50.63 v42.54,50.63
  Bottom 0.254: IC23.19 113.66,60.8 109.22,56.35 102.87,56.35 101.59,57.62 85.72,57.62 85.09,56.98 76.2,56.98 76.2,55.08 IC21.15 76.2,52.54 76.2,50.63 v42.54,50.63
E  (via drill 0.61)
  Top 0.254: IC18.9 116.2,8.73 116.2,10 IC18.10 | v29.84,23.96 29.84,62.7 29.21,63.34 29.21,79.21 30.48,80.48 IC17.34 | v63.49,16.98 66.04,19.52 | 66.04,19.52 77.47,30.95 77.47,51.27 78.73,52.54 IC21.14 | v73.02,11.9 66.04,18.88 66.04,19.52
  Bottom 0.254: v29.84,23.96 34.92,18.88 IC24.25 36.19,17.61 62.86,17.61 v63.49,16.98 | v73.02,11.9 77.47,11.9 80.01,14.44 111.76,14.44 115.56,10.63 IC18.10
EP
  Top 0.254: IC28.3 73.66,77.94 78.73,83.02 IC28.12
EP1\
  Top 0.254: IC28.2 71.75,77.3 77.47,83.02 77.47,85.56 78.1,86.19 86.36,86.19 86.36,85.56 IC28.9
FIRQ\  (via drill 0.61)
  Top 0.508: IC17.4 22.86,65.24 22.86,64.61 R15.1 22.86,63.34 v22.86,51.91 | IC24.37 34.92,49.37 34.92,50.63 IC24.38
  Bottom 0.508: v22.86,51.91 33.65,51.91 34.28,51.27 IC24.38
GND  (via drill 0.61)
  Top 0.508: 64.77,77.3 64.77,68.41 66.04,67.14 BYP19.2 | 64.77,77.3 66.04,78.58 BYP28.2 | 64.77,77.3 64.77,86.19 69.21,86.19 70.48,84.92 IC28.15 | BYP23.2 86.36,56.98 87.62,58.25 87.62,62.7 86.99,63.34 IC19.8 | BYP29.2 88.9,76.03 88.26,75.4 88.26,67.14 86.36,65.24 IC19.8 | BYP24.2 20.32,58.25 20.32,56.98 IC24.1 | C1.1 5.08,79.84 5.08,81.11 C2.2 | JP4.1 5.08,60.16 5.08,58.89 9.52,58.89 BYP25.2 10.15,58.25 10.15,57.62 13.96,53.81 IC25.19 14.6,53.17 10.15,48.73 10.15,31.58 BYP26.2 | BYP26.2 9.52,30.95 8.25,32.22 8.25,32.85 IC25.10 6.34,33.49 5.71,33.49 CORE-IO.10 5.08,32.85 3.17,30.95 CORE-IO.11 | 13.33,26.5 10.15,29.68 10.15,30.31 BYP26.2 | 13.33,26.5 13.96,25.87 IC26.19 | 13.33,26.5 13.33,11.27 8.25,6.18 IC26.10 | BYP18.2 107.31,5.55 107.95,5.55 IC18.7 | JP1.1 109.22,4.28 109.22,4.92 IC18.7 | C6.2 91.44,6.18 91.44,7.46 C4.2 92.07,8.09 93.98,10 C5.2 93.98,11.27 90.17,15.08 90.17,34.12 | IC22.14 123.82,25.23 118.11,19.52 111.12,19.52 111.12,7.46 109.85,6.18 IC18.7 | C7.2 50.79,21.42 50.79,22.7 C11.2 51.43,23.33 52.06,23.96 52.06,36.03 | BYP20.2 48.25,20.15 48.25,16.34 COM.5 47.62,15.08 43.17,15.08 COM.G2 | v78.73,35.39 78.73,26.5 BYP27.2 | 52.06,36.03 53.34,37.3 IC21.1 53.34,39.84 v53.34,43.65 55.88,46.19 55.88,52.54 IC21.23 | 52.06,36.03 50.79,34.76 IC20.15 | 90.17,34.12 88.9,35.39 BYP22.2 | 90.17,34.12 90.17,63.97 86.99,63.97 IC19.8
  Bottom 0.508: 123.19,63.97 123.19,65.88 123.82,65.88 IC29.14 | 123.19,63.97 123.19,60.16 123.82,59.52 124.45,59.52 124.45,47.46 IC23.14 | BYP29.2 88.26,76.67 86.99,76.67 IC28.8 85.72,77.3 84.45,78.58 67.31,78.58 66.67,79.21 BYP28.2 | 123.19,63.97 86.99,63.97 IC19.8 | IC25.19 16.51,53.81 19.05,56.35 IC24.1 21.59,56.35 33.02,56.35 34.28,57.62 41.27,57.62 R13.1 42.54,57.62 48.25,51.91 53.97,51.91 55.24,53.17 IC21.23 | 8.25,63.97 6.34,63.97 5.08,62.7 JP4.1 | 8.25,63.97 12.69,63.97 14.6,65.88 IC17.1 | 8.25,63.97 8.25,75.4 5.08,78.58 C1.1 | IC26.10 8.88,5.55 10.15,4.28 20.32,4.28 JP3.1 | BYP17.2 107.31,23.33 107.95,23.96 122.55,23.96 123.82,25.23 IC22.14 | BYP18.2 106.04,5.55 104.77,5.55 102.23,3.01 C3.2 100.96,3.01 98.42,5.55 92.07,5.55 C6.2 | IC27.7 77.47,8.09 78.73,6.82 89.53,6.82 90.8,8.09 C4.2 | BYP20.2 48.89,20.79 50.16,20.79 C7.2 | RS-232.2 41.9,28.41 42.54,27.77 51.43,27.77 52.06,27.14 52.06,23.96 50.79,23.96 C11.2 | COM.G1 63.49,15.08 61.59,16.98 48.89,16.98 48.25,16.34 COM.5 | BYP22.2 88.26,36.03 79.37,36.03 v78.73,35.39 61.59,35.39 | v53.34,43.65 51.43,43.65 BYP21.2 | 61.59,35.39 62.86,34.12 IC20.10 | 61.59,35.39 52.7,35.39 51.43,34.12 IC20.15
HLT\
  Top 0.254: R5.1 10.15,69.69 15.23,74.77 15.23,80.48 IC17.40
IO-E\  (via drill 0.61)
  Top 0.254: v25.39,16.98 22.86,19.52 22.86,41.11 21.59,42.38 17.14,42.38 17.14,44.28 16.51,44.92 17.14,45.55 17.14,64.61 16.51,65.24 16.51,75.4 21.59,80.48 21.59,83.02 24.12,85.56 58.41,85.56 58.41,86.19 60.32,88.1 87.62,88.1 87.62,74.13 86.36,72.86 IC19.9
  Bottom 0.254: v25.39,16.98 30.48,16.98 34.28,13.17 IC24.23
IO-F\  (via drill 0.61)
  Top 0.254: v73.66,44.92 73.66,39.84 IC21.9 | v83.81,44.92 83.81,62.7 IC19.7
  Bottom 0.254: v73.66,44.92 v83.81,44.92
IRQ\  (via drill 0.61)
  Top 0.254: IC21.7 68.58,39.84 68.58,40.48 R7.1 | v25.39,44.92 24.12,46.19 24.12,68.41 22.22,68.41 20.95,67.14 IC17.3
  Bottom 0.254: v25.39,44.92 26.03,44.28 32.38,44.28 34.28,42.38 47.62,42.38 48.89,41.11 53.97,41.11 54.6,41.74 68.58,41.74 R7.1
MR
  Bottom 0.254: R8.1 12.69,69.69 21.59,78.58 21.59,83.66 23.49,83.66 24.76,82.39 IC17.36
N$1
  Bottom 0.254: COM.4 50.79,15.08 51.43,14.44 56.51,14.44 57.14,13.81 COM.6
N$3
  Top 0.254: Q1.1 5.08,74.77 8.88,78.58 8.88,79.84 10.15,81.11 C2.1
  Bottom 0.254: IC17.38 19.68,81.11 18.41,79.84 12.69,79.84 10.79,81.75 C2.1
N$4
  Top 0.254: Q1.2 5.08,69.69 8.88,73.5 8.88,77.3 10.15,78.58 C1.2 10.15,79.84 11.42,81.11 11.42,83.66 15.87,83.66 17.14,82.39 IC17.39
N$5
  Bottom 0.254: IC25.18 16.51,51.27 19.05,53.81 IC24.2
N$6
  Top 0.254: IC18.5 108.58,11.27 108.58,12.54 IC18.4 108.58,13.81 108.58,15.08 IC18.3
N$21
  Top 0.254: IC18.1 107.95,20.79 107.31,20.79 R1.1 106.68,20.15 105.41,18.88 105.41,17.61 101.59,13.81 C3.1
N$22
  Top 0.254: IC18.2 107.95,18.25 107.31,18.25 R2.1 106.68,17.61 105.41,16.34 105.41,4.28 106.04,3.64 JP1.2
N$23  (via drill 0.61)
  Top 0.254: v65.4,10 62.22,13.17 62.22,29.68 59.68,32.22 59.68,35.39 58.41,36.66 58.41,37.3 IC21.3
  Bottom 0.254: IC21.3 59.05,37.94 60.32,37.94 IC21.4 | v65.4,10 67.31,10 70.48,13.17 74.93,13.17 IC27.5
N$24
  Top 0.254: IC26.18 15.87,23.96 17.14,25.23 17.14,30.31 19.68,32.85 IC24.10
N$25
  Top 0.254: IC26.17 15.87,21.42 17.78,23.33 17.78,28.41 19.68,30.31 IC24.11
N$27  (via drill 0.61)
  Top 0.254: IC27.2 75.56,20.15 74.29,18.88 R11.A 73.66,16.98 74.29,16.34 74.29,10.63 | v79.37,4.28 76.83,1.74 71.12,1.74 71.12,9.36 R11.S 71.75,10.63 74.29,10.63 | 74.29,10.63 74.93,10.63 IC27.6
  Bottom 0.254: v79.37,4.28 84.45,4.28 85.72,5.55 C6.1
N$28
  Top 0.254: IC27.1 76.83,22.7 78.1,21.42 78.1,6.82 76.83,5.55 R9.1
  Bottom 0.254: R9.1 76.83,5.55 79.37,3.01 83.18,3.01 R10.2
N$94
  Top 0.254: IC26.16 15.87,18.88 18.41,21.42 18.41,26.5 19.68,27.77 IC24.12
N$124
  Bottom 0.254: IC26.15 15.87,16.34 18.41,18.88 18.41,25.87 19.05,25.87 IC24.13
N$125
  Top 0.254: IC26.14 15.87,13.81 18.41,16.34 18.41,18.88 19.05,19.52 22.22,19.52 22.22,21.42 20.95,22.7 IC24.14
N$126
  Bottom 0.254: IC26.13 16.51,10.63 17.78,11.9 21.59,11.9 22.22,12.54 22.22,20.15 20.95,20.15 IC24.15
N$127
  Top 0.254: IC26.12 16.51,8.09 18.41,8.09 18.41,6.82 19.05,6.18 19.05,4.28 19.68,3.64 24.12,3.64 24.12,14.44 20.95,17.61 IC24.16
N$128
  Bottom 0.254: IC26.11 14.6,6.18 13.33,7.46 13.33,14.44 17.78,14.44 19.05,15.71 IC24.17
N$129
  Bottom 0.254: IC25.17 16.51,48.73 19.05,51.27 IC24.3
N$130
  Bottom 0.254: IC25.16 16.51,46.19 19.05,48.73 IC24.4
N$131
  Bottom 0.254: IC25.15 15.87,44.28 17.78,46.19 19.05,46.19 IC24.5
N$132
  Bottom 0.254: IC25.14 16.51,41.11 19.05,43.65 IC24.6
N$133
  Top 0.254: IC25.13 16.51,38.57 19.05,41.11 IC24.7
N$134
  Top 0.254: IC25.12 16.51,36.03 19.05,38.57 IC24.8
N$135
  Top 0.254: IC25.11 16.51,33.49 19.05,36.03 IC24.9
N$136
  Bottom 0.254: IC24.19 21.59,10.63 22.86,11.9 22.86,27.14 10.15,27.14 8.88,28.41 IC26.1
N$137  (via drill 0.61)
  Top 0.254: v34.92,60.16 37.46,57.62 37.46,55.71 36.19,54.45 IC24.39
  Bottom 0.254: v34.92,60.16 19.05,60.16 16.51,57.62 10.15,57.62 8.88,56.35 IC25.1
N$138  (via drill 0.61)
  Top 0.254: v28.57,9.36 v28.57,53.17 | v78.73,2.38 81.91,5.55 81.91,8.73 83.18,10 IC27.9
  Bottom 0.254: v28.57,53.17 31.11,53.17 34.28,56.35 IC24.40 | v28.57,9.36 31.75,6.18 43.17,6.18 47.62,1.74 78.1,1.74 v78.73,2.38
N$140
  Top 0.254: IC27.8 85.09,8.09 85.72,8.09 C4.1 | IC27.12 84.45,17.61 90.8,11.27 90.8,10.63 R4.1
  Bottom 0.254: R4.1 91.44,10 89.53,8.09 86.99,8.09 C4.1
N$141
  Top 0.254: IC27.13 85.09,20.79 88.9,20.79 88.9,18.88 R3.1
  Bottom 0.254: R3.1 89.53,18.25 90.8,18.25 R4.2
N$142
  Bottom 0.254: IC27.11 85.09,15.71 93.34,15.71 C5.1
N$143
  Bottom 0.254: R10.1 75.56,3.01 74.29,4.28 73.66,4.28 R11.E
N$145
  Top 0.254: COM.8 52.7,13.17 53.97,13.17 COM.7
N$147  (via drill 0.61)
  Top 0.254: IC18.12 116.2,16.34 116.2,17.61 IC18.13 | v68.58,26.5 64.77,30.31 64.77,36.03 63.49,37.3 IC21.5
  Bottom 0.254: v68.58,26.5 70.48,28.41 124.45,28.41 125.73,27.14 125.73,18.88 117.47,18.88 IC18.13
N$148
  Top 0.254: LED1.K 119.38,11.27 118.11,12.54 118.11,13.17 IC18.11
N$149
  Bottom 0.254: R12.1 86.99,18.25 88.26,16.98 110.48,16.98 115.56,11.9 120.01,11.9 121.28,10.63 LED1.A
N$150
  Top 0.254: IC21.24 53.34,55.08 53.34,56.35 JP2.1
  Bottom 0.254: R13.2 50.16,57.62 52.7,57.62 JP2.1
N$151  (via drill 0.61)
  Top 0.254: v38.09,8.09 36.82,6.82 26.67,6.82 v26.67,68.41
  Bottom 0.254: v38.09,8.09 71.75,8.09 73.02,9.36 89.53,9.36 90.17,10 90.17,11.27 90.8,11.9 94.61,11.9 97.15,9.36 111.76,9.36 115.56,5.55 IC18.8 | v26.67,68.41 34.28,76.03 67.94,76.03 IC28.1
N$153
  Top 0.254: IC20.7 64.13,25.23 65.4,25.23 IC20.8
N$154
  Bottom 0.254: C7.1 56.51,20.79 57.14,21.42 74.29,21.42 74.93,22.06 77.47,22.06 78.1,21.42 78.1,18.88 76.83,18.88 IC27.3
N$155  (via drill 0.61)
  Top 0.254: v58.41,30.95 58.41,27.14 IC20.5
  Bottom 0.254: v58.41,30.95 59.05,31.58 67.31,31.58 68.58,32.85 C9.2
N$156
  Bottom 0.254: IC20.4 56.51,26.5 58.41,28.41 67.94,28.41 C9.1
N$157
  Top 0.254: C8.2 46.35,30.95 49.52,27.77 49.52,20.15 50.16,19.52 52.06,19.52 52.06,22.7 53.34,23.96 53.34,24.6 IC20.3
N$158
  Top 0.254: C8.1 46.35,25.87 47.62,25.87 IC20.1
N$159
  Bottom 0.254: C11.1 56.51,23.33 57.14,23.96 59.05,23.96 60.32,25.23 IC20.6
N$160
  Bottom 0.254: C10.2 48.89,23.33 50.16,24.6 50.79,24.6 IC20.2
NMI\  (via drill 0.61)
  Top 0.254: v17.78,44.92 17.78,65.24 IC17.2
  Bottom 0.254: v17.78,44.92 24.12,44.92 25.39,46.19 31.11,46.19 32.38,44.92 72.39,44.92 73.66,43.65 85.72,43.65 R6.1
PIA-A0
  Top 0.254: IC25.2 6.98,53.17 2.54,48.73 2.54,44.28 CORE-IO.1
PIA-A1
  Top 0.254: IC25.3 6.98,50.63 5.08,48.73 5.08,44.28 CORE-IO.2
PIA-A2
  Bottom 0.254: IC25.4 6.98,48.09 3.81,44.92 3.81,43.02 2.54,41.74 CORE-IO.3
PIA-A3
  Top 0.254: IC25.5 8.25,45.55 9.52,44.28 9.52,43.02 8.88,42.38 5.08,42.38 5.08,41.74 CORE-IO.4
PIA-A4
  Bottom 0.254: IC25.6 8.25,43.02 9.52,41.74 9.52,39.84 4.44,39.84 3.17,38.57 CORE-IO.5
PIA-A5
  Top 0.254: IC25.7 6.98,40.48 5.71,39.2 5.71,38.57 CORE-IO.6
PIA-A6
  Bottom 0.254: IC25.8 6.98,37.94 6.34,37.3 4.44,37.3 3.17,36.03 CORE-IO.7
PIA-A7
  Top 0.254: IC25.9 6.34,36.03 5.71,36.03 CORE-IO.8
PIA-B0
  Bottom 0.254: IC26.2 6.98,26.5 6.34,27.14 4.44,27.14 3.17,28.41 CORE-IO.13
PIA-B1
  Top 0.254: IC26.3 6.98,22.7 6.34,22.7 5.71,22.06 3.81,22.06 3.81,26.5 5.08,27.77 CORE-IO.14
PIA-B2
  Bottom 0.254: IC26.4 6.98,20.15 6.34,19.52 4.44,19.52 3.81,20.15 3.81,25.23 2.54,25.23 CORE-IO.15
PIA-B3
  Top 0.254: IC26.5 8.25,18.88 9.52,20.15 9.52,23.96 8.88,24.6 5.08,24.6 5.08,25.23 CORE-IO.16
PIA-B4
  Bottom 0.254: IC26.6 6.34,15.71 2.54,19.52 1.9,19.52 1.27,20.15 1.27,23.33 1.9,23.33 CORE-IO.17
PIA-B5
  Bottom 0.254: IC26.7 8.25,13.81 9.52,15.08 9.52,22.06 5.71,22.06 5.08,22.7 CORE-IO.18
PIA-B6
  Top 0.254: IC26.8 6.98,11.27 2.54,15.71 2.54,20.15 CORE-IO.19
PIA-B7
  Top 0.254: IC26.9 8.25,8.73 9.52,10 9.52,16.34 8.88,16.98 5.08,16.98 5.08,20.15 CORE-IO.20
R/W\  (via drill 0.61)
  Top 0.254: 83.18,43.02 81.28,44.92 81.28,52.54 IC21.13 | 83.18,43.02 v83.81,42.38 | IC24.21 34.92,8.73 33.65,10 33.65,64.61 34.28,65.24 34.28,77.94 35.55,79.21 35.55,80.48 IC17.32 | 83.18,43.02 80.01,39.84 80.01,7.46 76.83,4.28 74.93,4.28 74.93,3.64 v74.29,3.01
  Bottom 0.254: v83.81,42.38 86.99,42.38 87.62,43.02 92.07,43.02 93.34,41.74 IC22.27 | v74.29,3.01 73.66,3.64 46.98,3.64 43.81,6.82 38.09,6.82 36.82,8.09 IC24.21
RST\  (via drill 0.61)
  Top 0.254: v25.39,43.65 21.59,47.46 18.41,47.46 18.41,64.61 19.05,65.24 19.05,76.67 22.86,80.48 IC17.37 | v104.14,8.09 92.7,19.52 92.7,69.69 92.07,70.32 92.07,79.21 v92.7,79.84
  Bottom 0.254: v25.39,43.65 31.75,43.65 34.28,41.11 IC24.34 | v104.14,8.09 107.95,8.09 IC18.6 | v92.7,79.84 85.72,79.84 84.45,81.11 65.4,81.11 64.13,79.84 24.76,79.84 23.49,81.11 IC17.37
RX
  Top 0.254: IC20.12 58.41,34.76 55.88,37.3 IC21.2
RXD  (via drill 0.61)
  Top 0.254: IC20.13 55.88,32.22 57.14,30.95 57.14,19.52 60.32,16.34 60.32,15.08 59.68,14.44 53.34,14.44 53.34,15.08 COM.3 53.34,16.34 v53.34,22.06
  Bottom 0.254: v53.34,22.06 47.62,22.06 45.08,24.6 43.17,24.6 41.9,25.87 RS-232.3
TX
  Top 0.254: IC20.11 60.95,34.76 62.22,36.03 62.22,39.84 62.86,40.48 66.04,40.48 66.04,39.84 IC21.6
TXD
  Top 0.254: COM.2 55.88,16.34 54.6,17.61 54.6,30.95 53.34,32.22 IC20.14
  Bottom 0.254: IC20.14 52.7,32.85 49.52,29.68 45.08,29.68 43.81,30.95 41.9,30.95 RS-232.1
VCC
  Top 0.508: 88.26,10.63 88.26,6.82 85.72,6.82 84.45,5.55 R9.2 | 88.26,10.63 R3.2 88.26,10.63 | 88.26,10.63 86.99,10.63 R12.2 85.72,10.63 85.72,11.27 84.45,12.54 IC27.10 83.18,13.81 81.91,15.08 81.91,28.41 | BYP29.1 89.53,81.75 90.8,81.75 IC29.28 91.44,80.48 91.44,67.78 IC29.1 91.44,65.24 91.44,62.7 IC23.28 91.44,60.16 91.44,47.46 IC23.1 91.44,44.92 91.44,42.38 IC22.28 | R2.2 99.06,18.88 99.06,20.15 R1.2 99.69,20.79 101.59,22.7 BYP17.1 | IC27.14 83.81,23.96 83.81,25.23 BYP27.1 83.81,26.5 81.91,28.41 | R6.2 86.36,50.63 88.9,48.09 88.9,41.74 BYP22.1 | 81.91,28.41 81.28,29.04 81.28,37.3 IC21.12 | IC20.16 48.25,34.76 50.79,37.3 50.79,37.94 BYP21.1 50.79,39.2 52.06,40.48 52.06,44.28 54.6,46.82 54.6,55.08 55.88,56.35 JP2.2 | BYP19.1 66.67,71.59 67.94,71.59 IC19.16 68.58,72.86 67.31,74.13 67.31,84.29 | 67.31,84.29 67.94,84.29 IC28.16 | 67.31,84.29 66.67,84.29 BYP28.1 | R15.2 30.48,64.61 30.48,65.24 IC17.7 30.48,67.78 30.48,77.94 33.02,80.48 IC17.33 | C10.1 43.17,22.7 43.17,21.42 BYP20.1 42.54,20.79 36.82,15.08 36.82,14.44 | 36.82,14.44 36.19,15.08 IC24.24 | 36.82,14.44 37.46,13.81 37.46,12.54 36.19,11.27 IC24.22 | IC26.20 15.23,29.04 15.23,30.31 BYP26.1 | R8.2 12.06,76.67 10.79,76.67 R5.2 10.15,76.03 9.52,75.4 9.52,70.32 7.62,68.41 7.62,62.7 JP4.2 8.25,60.8 15.23,60.8 15.23,59.52 BYP25.1 15.23,58.25 15.23,56.98 IC25.20 | R7.2 76.2,40.48 76.2,39.84 IC21.10
  Bottom 0.508: BYP18.1 106.04,10.63 104.77,11.9 95.88,11.9 94.61,13.17 85.09,13.17 IC27.10 | BYP23.1 86.99,61.43 90.8,61.43 IC23.28 92.07,60.8 93.34,60.8 IC23.27 | IC18.14 115.56,20.79 114.3,22.06 103.5,22.06 102.23,23.33 BYP17.1 | IC21.8 71.75,37.94 73.02,36.66 74.29,36.66 75.56,37.94 IC21.10 76.83,39.2 78.1,40.48 83.18,40.48 | 83.18,40.48 83.81,41.11 88.26,41.11 BYP22.1 89.53,41.11 90.8,41.11 IC22.28 | 83.18,40.48 81.91,39.2 IC21.12 | R1.2 98.42,20.79 95.88,23.33 85.09,23.33 IC27.14 83.18,22.7 76.83,16.34 IC27.4 74.93,15.71 69.21,15.71 66.67,18.25 43.81,18.25 43.17,18.88 43.17,20.15 BYP20.1 | BYP19.1 65.4,71.59 63.49,69.69 32.38,69.69 30.48,67.78 IC17.7 | JP2.2 55.88,58.89 53.34,61.43 45.71,61.43 43.81,63.34 30.48,63.34 R15.2 29.84,63.97 27.94,62.06 8.25,62.06 JP4.2 | R14.2 17.78,6.18 19.05,7.46 19.68,7.46 IC24.20 21.59,8.09 24.12,10.63 34.28,10.63 IC24.22 | 3.17,32.22 2.54,32.85 CORE-IO.9 | 3.17,32.22 4.44,30.95 CORE-IO.12 | 13.33,32.22 14.6,30.95 BYP26.1 | 13.33,32.22 3.17,32.22 | BYP24.1 24.76,58.89 23.49,57.62 17.78,57.62 16.51,56.35 IC25.20 13.96,56.35 13.33,56.35 13.33,32.22 | IC24.24 34.92,16.34 21.59,29.68 17.78,29.68 16.51,28.41 IC26.20

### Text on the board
Top: Component Side
Bottom: Solder side | PA8PDP/VRS
tPlace: RealConsole CORE - Rev.1 | +
tValues: - | + | TxD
